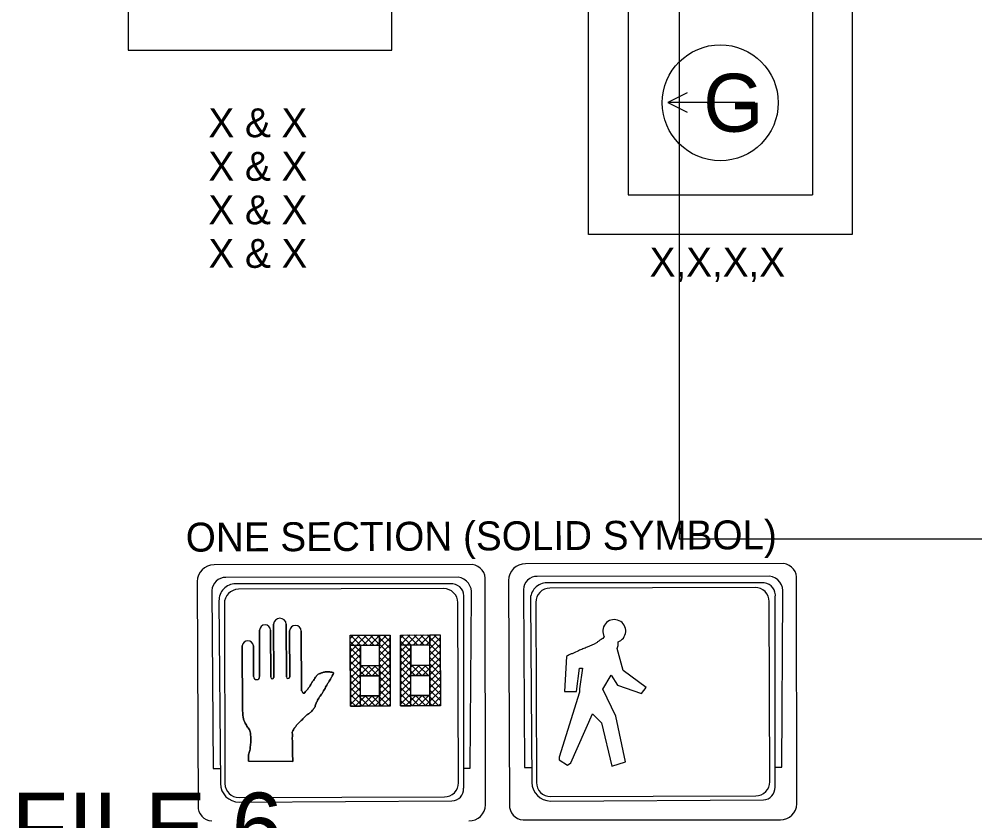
# Model space of a CAD drawing. Extents: x -218554 to 420114, y -565956 to -483460.
# Drawn here: x 418533 to 418625.5, y -565657.6 to -565580 of the extents above; entities that cross this region are included whole.
import ezdxf

# ---------------------------------------------------------------- set-up
doc = ezdxf.new("R2010")
doc.units = 0
for name, color, linetype in [('C-ANNO-TEXT', 7, 'Continuous'), ('Level 1', 7, 'Continuous'), ('Level 61', 7, 'Continuous'), ('Template', 7, 'Continuous')]:
    doc.layers.add(name, color=color, linetype=linetype)

msp = doc.modelspace()

# ---------------------------------------------------------------- linework, layer by layer
at = {"layer": 'Level 1'}
for p, q in [((418576.864, -565632.836), (418551.866, -565632.855)), ((418607.001, -565632.731), (418582.003, -565632.751)), ((418605.626, -565633.944), (418583.146, -565633.972)), ((418550.232, -565634.478), (418550.326, -565656.171)), ((418575.49, -565634.049), (418553.009, -565634.076)), ((418574.974, -565634.69), (418553.941, -565634.694)), ((418578.135, -565656.092), (418578.111, -565634.419)), ((418580.369, -565634.373), (418580.463, -565656.066)), ((418605.111, -565634.585), (418584.078, -565634.59)), ((418608.272, -565655.988), (418608.248, -565634.315)), ((418552.343, -565636.346), (418552.492, -565654.023)), ((418576.026, -565654.476), (418576.048, -565636.101)), ((418582.48, -565636.241), (418582.629, -565653.919)), ((418606.163, -565654.372), (418606.185, -565635.996)), ((418558.861, -565638.593), (418558.879, -565643.702)), ((418558.879, -565643.702), (418558.861, -565638.593)), ((418556.281, -565643.662), (418556.265, -565639.166)), ((418556.265, -565639.166), (418556.281, -565643.662)), ((418557.332, -565639.175), (418557.348, -565643.732)), ((418557.348, -565643.732), (418557.332, -565639.175)), ((418557.654, -565643.756), (418557.636, -565638.609)), ((418557.636, -565638.609), (418557.654, -565643.756)), ((418559.186, -565643.726), (418559.17, -565639.242)), ((418559.17, -565639.242), (418559.186, -565643.726)), ((418560.311, -565639.275), (418560.331, -565645.047)), ((418560.331, -565645.047), (418560.311, -565639.275)), ((418565.036, -565639.982), (418565.354, -565639.661)), ((418565.037, -565640.262), (418566.04, -565641.258)), ((418565.038, -565640.62), (418565.992, -565639.659)), ((418565.04, -565641.258), (418566.63, -565639.657)), ((418565.073, -565639.662), (418566.076, -565640.659)), ((418565.711, -565639.66), (418566.714, -565640.656)), ((418566.271, -565640.658), (418567.268, -565639.655)), ((418566.349, -565639.658), (418567.352, -565640.654)), ((418566.909, -565640.656), (418567.906, -565639.652)), ((418566.986, -565639.656), (418568.889, -565641.545)), ((418567.547, -565640.654), (418568.543, -565639.65)), ((418567.624, -565639.653), (418568.887, -565640.907)), ((418567.887, -565640.951), (418568.883, -565639.948)), ((418568.262, -565639.651), (418568.884, -565640.269)), ((418569.899, -565639.965), (418570.218, -565639.644)), ((418569.9, -565640.245), (418570.903, -565641.241)), ((418569.901, -565640.603), (418570.855, -565639.642)), ((418569.903, -565641.241), (418571.493, -565639.64)), ((418569.936, -565639.645), (418570.94, -565640.642)), ((418570.574, -565639.643), (418571.577, -565640.64)), ((418571.135, -565640.641), (418572.131, -565639.638)), ((418571.212, -565639.641), (418572.215, -565640.637)), ((418571.772, -565640.639), (418572.769, -565639.635)), ((418571.85, -565639.639), (418573.752, -565641.528)), ((418572.41, -565640.637), (418573.407, -565639.633)), ((418572.487, -565639.636), (418573.75, -565640.89)), ((418572.75, -565640.935), (418573.746, -565639.931)), ((418573.125, -565639.634), (418573.748, -565640.252)), ((418591.098, -565640.249), (418591.099, -565640.249)), ((418554.626, -565646.906), (418554.604, -565640.693)), ((418554.604, -565640.693), (418554.626, -565646.906)), ((418555.67, -565640.701), (418555.68, -565643.664)), ((418555.68, -565643.664), (418555.67, -565640.701)), ((418565.039, -565640.899), (418566.042, -565641.896)), ((418565.042, -565641.896), (418566.039, -565640.892)), ((418567.888, -565641.186), (418568.891, -565642.183)), ((418567.889, -565641.589), (418568.885, -565640.586)), ((418567.891, -565642.227), (418568.888, -565641.224)), ((418569.902, -565640.883), (418570.906, -565641.879)), ((418569.906, -565641.879), (418570.902, -565640.875)), ((418572.751, -565641.169), (418573.754, -565642.166)), ((418572.752, -565641.572), (418573.749, -565640.569)), ((418572.754, -565642.21), (418573.751, -565641.207)), ((418565.041, -565641.537), (418567.107, -565643.589)), ((418565.043, -565642.175), (418566.469, -565643.591)), ((418565.044, -565642.533), (418566.041, -565641.53)), ((418565.047, -565643.171), (418566.043, -565642.168)), ((418567.175, -565643.588), (418568.89, -565641.861)), ((418567.89, -565641.824), (418568.893, -565642.82)), ((418569.904, -565641.52), (418571.97, -565643.572)), ((418569.906, -565642.158), (418571.332, -565643.574)), ((418569.908, -565642.517), (418570.904, -565641.513)), ((418569.91, -565643.154), (418570.906, -565642.151)), ((418572.038, -565643.571), (418573.753, -565641.845)), ((418572.753, -565641.807), (418573.756, -565642.804)), ((418565.045, -565642.813), (418566.049, -565643.809)), ((418565.049, -565643.809), (418566.258, -565642.591)), ((418565.051, -565644.447), (418566.896, -565642.589)), ((418566.045, -565642.592), (418567.892, -565642.586)), ((418566.537, -565643.59), (418567.534, -565642.587)), ((418566.741, -565642.59), (418567.744, -565643.586)), ((418567.379, -565642.588), (418568.898, -565644.096)), ((418567.813, -565643.586), (418568.892, -565642.499)), ((418567.892, -565642.462), (418568.895, -565643.458)), ((418567.898, -565644.14), (418568.894, -565643.137)), ((418569.909, -565642.796), (418570.912, -565643.793)), ((418569.912, -565643.792), (418571.121, -565642.575)), ((418569.914, -565644.43), (418571.759, -565642.572)), ((418570.908, -565642.575), (418572.756, -565642.569)), ((418571.4, -565643.574), (418572.397, -565642.57)), ((418571.604, -565642.573), (418572.608, -565643.569)), ((418572.242, -565642.571), (418573.761, -565644.079)), ((418572.676, -565643.569), (418573.755, -565642.482)), ((418572.755, -565642.445), (418573.759, -565643.441)), ((418572.761, -565644.124), (418573.758, -565643.12)), ((418565.048, -565643.451), (418566.051, -565644.447)), ((418565.05, -565644.089), (418566.053, -565645.085)), ((418565.053, -565645.085), (418566.05, -565644.081)), ((418566.048, -565643.592), (418567.896, -565643.586)), ((418567.896, -565643.737), (418568.9, -565644.734)), ((418567.9, -565644.778), (418568.897, -565643.775)), ((418569.911, -565643.434), (418570.914, -565644.43)), ((418569.913, -565644.072), (418570.917, -565645.068)), ((418569.917, -565645.068), (418570.913, -565644.064)), ((418570.911, -565643.575), (418572.759, -565643.569)), ((418572.76, -565643.72), (418573.763, -565644.717)), ((418572.763, -565644.761), (418573.76, -565643.758)), ((418565.052, -565644.726), (418566.861, -565646.523)), ((418565.056, -565645.722), (418566.052, -565644.719)), ((418566.803, -565646.523), (418568.899, -565644.413)), ((418567.441, -565646.521), (418568.901, -565645.05)), ((418567.899, -565644.375), (418568.902, -565645.372)), ((418567.901, -565645.013), (418568.904, -565646.009)), ((418569.915, -565644.709), (418571.724, -565646.506)), ((418569.919, -565645.706), (418570.915, -565644.702)), ((418571.666, -565646.506), (418573.762, -565644.396)), ((418572.304, -565646.504), (418573.764, -565645.034)), ((418572.762, -565644.358), (418573.765, -565645.355)), ((418572.764, -565644.996), (418573.768, -565645.993)), ((418565.054, -565645.364), (418566.223, -565646.525)), ((418565.056, -565646.002), (418565.585, -565646.527)), ((418565.058, -565646.36), (418566.054, -565645.357)), ((418565.527, -565646.527), (418566.524, -565645.524)), ((418566.165, -565646.525), (418567.162, -565645.522)), ((418566.495, -565645.524), (418567.499, -565646.521)), ((418567.133, -565645.522), (418568.137, -565646.518)), ((418567.771, -565645.52), (418568.774, -565646.516)), ((418568.079, -565646.519), (418568.903, -565645.688)), ((418569.918, -565645.347), (418571.086, -565646.508)), ((418569.92, -565645.985), (418570.449, -565646.51)), ((418569.921, -565646.343), (418570.918, -565645.34)), ((418570.391, -565646.51), (418571.387, -565645.507)), ((418571.028, -565646.508), (418572.025, -565645.505)), ((418571.359, -565645.507), (418572.362, -565646.504)), ((418571.996, -565645.505), (418573, -565646.501)), ((418572.634, -565645.503), (418573.638, -565646.499)), ((418572.942, -565646.502), (418573.766, -565645.671)), ((418568.716, -565646.516), (418568.905, -565646.326)), ((418573.58, -565646.499), (418573.769, -565646.309)), ((418555.201, -565651.866), (418559.494, -565651.878)), ((418559.477, -565651.876), (418555.224, -565651.89)), ((418559.497, -565651.881), (418559.477, -565651.876)), ((418554.296, -565655.815), (418574.892, -565655.706)), ((418584.433, -565655.711), (418605.029, -565655.602)), ((418581.777, -565657.529), (418606.674, -565657.529))]:
    msp.add_line(p, q, dxfattribs=at)
for points in [[(418551.667, -565635.34), (418551.779, -565652.577), (418552.503, -565652.574)], [(418574.091, -565635.154), (418554.225, -565635.223)], [(418576.014, -565652.543), (418576.666, -565652.54), (418576.772, -565635.753)], [(418581.804, -565635.236), (418581.916, -565652.472), (418582.64, -565652.47)], [(418604.228, -565635.049), (418584.362, -565635.118)], [(418606.151, -565652.438), (418606.803, -565652.435), (418606.909, -565635.648)], [(418552.866, -565636.59), (418552.926, -565654.022)], [(418575.519, -565653.944), (418575.459, -565636.512)], [(418583.003, -565636.486), (418583.063, -565653.917)], [(418605.656, -565653.839), (418605.596, -565636.407)], [(418585.986, -565641.717), (418585.798, -565645.1), (418586.959, -565645.096), (418587.252, -565642.858), (418587.518, -565642.868), (418587.234, -565644.851), (418587.235, -565645.187), (418585.27, -565651.464), (418585.271, -565651.709), (418586.067, -565652.257), (418586.403, -565652.011), (418588.495, -565647.262), (418589.354, -565648.147), (418590.376, -565652.333), (418591.69, -565651.931), (418590.758, -565647.5), (418589.495, -565644.874), (418590.316, -565643.525), (418590.9, -565644.501), (418593.225, -565645.319), (418593.682, -565644.737), (418591.466, -565643.07), (418590.887, -565640.96), (418590.978, -565640.647), (418590.983, -565640.307), (418591.098, -565640.249)], [(418567.892, -565642.586), (418567.886, -565640.652), (418566.038, -565640.659), (418566.045, -565642.592)], [(418572.756, -565642.569), (418572.749, -565640.636), (418570.901, -565640.642), (418570.908, -565642.575)], [(418567.896, -565643.586), (418567.903, -565645.519), (418566.055, -565645.526), (418566.048, -565643.592)], [(418572.759, -565643.569), (418572.766, -565645.502), (418570.918, -565645.509), (418570.911, -565643.575)], [(418584.432, -565655.276), (418604.298, -565655.207)], [(418554.295, -565655.381), (418574.161, -565655.312)]]:
    msp.add_lwpolyline(points, dxfattribs=at)
for points in [[(418565.034, -565639.662), (418568.882, -565639.649), (418568.906, -565646.516), (418565.058, -565646.529)], [(418565.034, -565639.662), (418567.885, -565639.66), (418567.886, -565640.652), (418565.035, -565640.655)], [(418567.885, -565639.66), (418568.901, -565639.659), (418568.906, -565646.516), (418567.89, -565646.516)], [(418569.898, -565639.645), (418573.745, -565639.632), (418573.769, -565646.499), (418569.922, -565646.512)], [(418569.898, -565639.645), (418572.748, -565639.643), (418572.749, -565640.636), (418569.899, -565640.638)], [(418572.748, -565639.643), (418573.764, -565639.642), (418573.769, -565646.499), (418572.753, -565646.5)], [(418565.058, -565646.529), (418566.043, -565646.528), (418566.038, -565640.659), (418565.054, -565640.66)], [(418569.922, -565646.512), (418570.906, -565646.511), (418570.901, -565640.642), (418569.917, -565640.643)], [(418566.045, -565642.592), (418567.895, -565642.591), (418567.896, -565643.586), (418566.045, -565643.587)], [(418570.908, -565642.575), (418572.758, -565642.574), (418572.759, -565643.569), (418570.909, -565643.57)], [(418566.055, -565645.526), (418567.889, -565645.524), (418567.89, -565646.516), (418566.056, -565646.518)], [(418570.918, -565645.509), (418572.753, -565645.507), (418572.753, -565646.5), (418570.919, -565646.501)]]:
    msp.add_lwpolyline(points, close=True, dxfattribs=at)
for centre, radius, start, end in [((418551.861, -565634.484), 1.629, 89.82106, 179.82106), ((418576.696, -565634.251), 1.425, 353.22698, 83.22698), ((418581.998, -565634.379), 1.629, 89.82106, 179.82106), ((418606.833, -565634.147), 1.425, 353.22698, 83.22698), ((418583.107, -565635.274), 1.303, 88.32188, 178.32188), ((418605.415, -565635.437), 1.508, 351.95736, 81.95736), ((418552.97, -565635.379), 1.303, 88.32188, 178.32188), ((418553.968, -565636.319), 1.625, 90.92866, 180.92866), ((418574.805, -565635.932), 1.254, 352.27295, 82.27295), ((418575.278, -565635.542), 1.508, 351.95736, 81.95736), ((418584.105, -565636.214), 1.625, 90.92866, 180.92866), ((418604.942, -565635.827), 1.254, 352.27295, 82.27295), ((418554.229, -565636.586), 1.363, 90.1989, 180.1989), ((418574.096, -565636.517), 1.363, 0.1989, 90.1989), ((418584.366, -565636.481), 1.363, 90.1989, 180.1989), ((418604.233, -565636.412), 1.363, 0.1989, 90.1989), ((418558.249, -565638.637), 0.614, 4.09887, 177.44568), ((418558.249, -565638.637), 0.614, 4.09887, 177.44568), ((418590.601, -565639.258), 1.11, 296.66377, 209.00111), ((418556.798, -565639.201), 0.534, 2.86645, 176.21327), ((418556.798, -565639.201), 0.534, 2.86645, 176.21327), ((418559.739, -565639.291), 0.571, 1.67648, 175.02329), ((418559.739, -565639.291), 0.571, 1.67648, 175.02329), ((418555.137, -565640.728), 0.534, 2.86645, 176.21327), ((418555.137, -565640.728), 0.534, 2.86645, 176.21327), ((418555.981, -565643.663), 0.3, 180.1989, 0.1989), ((418555.981, -565643.663), 0.3, 180.1989, 0.1989), ((418557.501, -565643.744), 0.154, 175.62151, 355.62151), ((418557.501, -565643.744), 0.154, 175.62151, 355.62151), ((418559.03, -565643.712), 0.156, 175.0942, 355.0942), ((418559.03, -565643.712), 0.156, 175.0942, 355.0942), ((418554.29, -565654.017), 1.798, 180.1989, 270.1989), ((418554.29, -565654.017), 1.363, 180.1989, 270.1989), ((418574.156, -565653.948), 1.363, 270.1989, 0.1989), ((418584.427, -565653.913), 1.798, 180.1989, 270.1989), ((418584.427, -565653.913), 1.363, 180.1989, 270.1989), ((418604.293, -565653.844), 1.363, 270.1989, 0.1989), ((418574.844, -565654.524), 1.182, 272.30854, 2.30854), ((418604.981, -565654.42), 1.182, 272.30854, 2.30854), ((418551.714, -565656.244), 1.391, 176.97995, 266.97995), ((418576.565, -565656.063), 1.57, 268.95937, 358.95937), ((418581.851, -565656.139), 1.391, 176.97995, 266.97995), ((418606.702, -565655.958), 1.57, 268.95937, 358.95937)]:
    msp.add_arc(centre, radius, start, end, dxfattribs=at)
for points in [[(418589.63, -565639.795), (418589.501, -565639.978), (418589.326, -565640.072), (418589.112, -565640.226), (418588.872, -565640.404), (418587.984, -565640.811), (418587.556, -565640.996), (418587.138, -565641.16), (418586.58, -565641.427), (418586.311, -565641.528), (418585.986, -565641.717)], [(418560.328, -565645.045), (418560.37, -565645.054), (418560.429, -565645.172), (418560.504, -565645.261), (418560.548, -565645.274), (418560.621, -565645.261), (418560.665, -565645.2), (418560.798, -565645.052), (418560.9, -565644.934), (418560.958, -565644.847), (418561.018, -565644.772), (418561.122, -565644.639), (418561.178, -565644.52), (418561.267, -565644.358), (418561.325, -565644.269), (418561.427, -565644.107), (418561.545, -565643.959), (418561.633, -565643.812), (418561.735, -565643.664), (418561.823, -565643.559), (418561.956, -565643.442), (418562.118, -565643.381), (418562.206, -565643.337), (418562.339, -565643.293), (418562.456, -565643.248), (418562.634, -565643.218), (418562.782, -565643.217), (418562.972, -565643.216), (418563.149, -565643.231), (418563.355, -565643.259), (418563.414, -565643.289), (418563.43, -565643.332), (418563.341, -565643.524), (418563.283, -565643.627), (418563.225, -565643.732), (418563.166, -565643.85), (418563.137, -565643.923), (418563.019, -565644.116), (418562.843, -565644.383), (418562.609, -565644.811), (418562.316, -565645.298), (418562.082, -565645.639), (418561.949, -565645.86), (418561.832, -565646.066), (418561.765, -565646.232), (418561.729, -565646.315), (418561.6, -565646.672), (418561.394, -565646.923), (418561.233, -565647.101), (418560.996, -565647.279), (418560.85, -565647.383), (418560.468, -565647.768), (418560.131, -565648.092), (418559.91, -565648.314), (418559.72, -565648.564), (418559.625, -565648.675), (418559.544, -565648.832), (418559.456, -565648.979), (418559.457, -565649.304), (418559.443, -565649.595), (418559.444, -565649.862), (418559.461, -565650.215), (418559.462, -565650.554), (418559.464, -565651.1), (418559.479, -565651.54), (418559.494, -565651.702), (418559.494, -565651.82), (418559.494, -565651.878)], [(418559.494, -565651.878), (418559.494, -565651.82), (418559.494, -565651.702), (418559.479, -565651.54), (418559.464, -565651.1), (418559.462, -565650.554), (418559.461, -565650.215), (418559.444, -565649.862), (418559.443, -565649.595), (418559.457, -565649.304), (418559.456, -565648.979), (418559.544, -565648.832), (418559.625, -565648.675), (418559.72, -565648.564), (418559.91, -565648.314), (418560.131, -565648.092), (418560.468, -565647.768), (418560.85, -565647.383), (418560.996, -565647.279), (418561.233, -565647.101), (418561.394, -565646.923), (418561.6, -565646.672), (418561.729, -565646.315), (418561.765, -565646.232), (418561.832, -565646.066), (418561.949, -565645.86), (418562.082, -565645.639), (418562.316, -565645.298), (418562.609, -565644.811), (418562.843, -565644.383), (418563.019, -565644.116), (418563.137, -565643.923), (418563.166, -565643.85), (418563.225, -565643.732), (418563.283, -565643.627), (418563.341, -565643.524), (418563.43, -565643.332), (418563.414, -565643.289), (418563.355, -565643.259), (418563.149, -565643.231), (418562.972, -565643.216), (418562.782, -565643.217), (418562.634, -565643.218), (418562.456, -565643.248), (418562.339, -565643.293), (418562.206, -565643.337), (418562.118, -565643.381), (418561.956, -565643.442), (418561.823, -565643.559), (418561.735, -565643.664), (418561.633, -565643.812), (418561.545, -565643.959), (418561.427, -565644.107), (418561.325, -565644.269), (418561.267, -565644.358), (418561.178, -565644.52), (418561.122, -565644.639), (418561.018, -565644.772), (418560.958, -565644.847), (418560.9, -565644.934), (418560.798, -565645.052), (418560.665, -565645.2), (418560.621, -565645.261), (418560.548, -565645.274), (418560.504, -565645.261), (418560.429, -565645.172), (418560.37, -565645.054), (418560.328, -565645.045)], [(418555.201, -565651.866), (418555.2, -565651.63), (418555.214, -565651.232), (418555.33, -565650.819), (418555.388, -565650.347), (418555.431, -565650.082), (418555.429, -565649.565), (418555.384, -565649.138), (418555.339, -565648.917), (418555.116, -565648.548), (418554.88, -565648.181), (418554.745, -565647.872), (418554.686, -565647.548), (418554.64, -565647.297), (418554.64, -565647.136), (418554.626, -565646.906)], [(418554.626, -565646.906), (418554.64, -565647.136), (418554.64, -565647.297), (418554.686, -565647.548), (418554.745, -565647.872), (418554.88, -565648.181), (418555.116, -565648.548), (418555.339, -565648.917), (418555.384, -565649.138), (418555.429, -565649.565), (418555.431, -565650.082), (418555.388, -565650.347), (418555.33, -565650.819), (418555.214, -565651.232), (418555.2, -565651.63), (418555.201, -565651.866)]]:
    msp.add_spline(points, degree=3, dxfattribs=at)
at = {"layer": 'Level 61'}
for p, q in [((418591.934, -565579.206), (418591.934, -565597.057)), ((418609.785, -565579.206), (418609.785, -565597.057)), ((418604.197, -565588.107), (418595.783, -565588.107)), ((418591.934, -565597.057), (418609.785, -565597.057))]:
    msp.add_line(p, q, dxfattribs=at)
for points in [[(418569.062, -565583.031), (418569.062, -565521.827), (418543.561, -565521.827), (418543.561, -565583.031)], [(418588.109, -565600.882), (418588.109, -565521.827), (418613.611, -565521.827), (418613.611, -565600.882)]]:
    msp.add_lwpolyline(points, close=True, dxfattribs=at)
msp.add_lwpolyline([(418597.653, -565587.172), (418595.783, -565588.107), (418597.653, -565589.042)], dxfattribs=at)
msp.add_circle((418600.86, -565588.131), 5.609, dxfattribs=at)
at = {"layer": 'Template'}
msp.add_lwpolyline([(418728.858, -565470.289), (418596.867, -565470.289), (418596.867, -565630.346), (418728.858, -565630.346)], close=True, dxfattribs=at)

# ---------------------------------------------------------------- texts
at = {"layer": 'C-ANNO-TEXT'}
for s, p in [('X & X', (418551.323, -565591.468)), ('X & X', (418551.323, -565595.681)), ('X & X', (418551.323, -565599.895)), ('X & X', (418551.323, -565604.109)), ('X,X,X,X', (418594.023, -565604.95))]:
    msp.add_text(s, height=2.8, dxfattribs=at).set_placement(p)
msp.add_text('ONE SECTION (SOLID SYMBOL)', height=2.8, rotation=0.24551, dxfattribs=at).set_placement((418549.133, -565631.579))
at = {"layer": 'Level 61'}
msp.add_text('G', height=5.609, dxfattribs=at).set_placement((418599.212, -565590.935))
at = {"layer": 'Template'}
msp.add_text('FILE 6', height=6.6667, rotation=360, dxfattribs=at).set_placement((418532.27, -565661.57))

doc.saveas('drawing.dxf')
